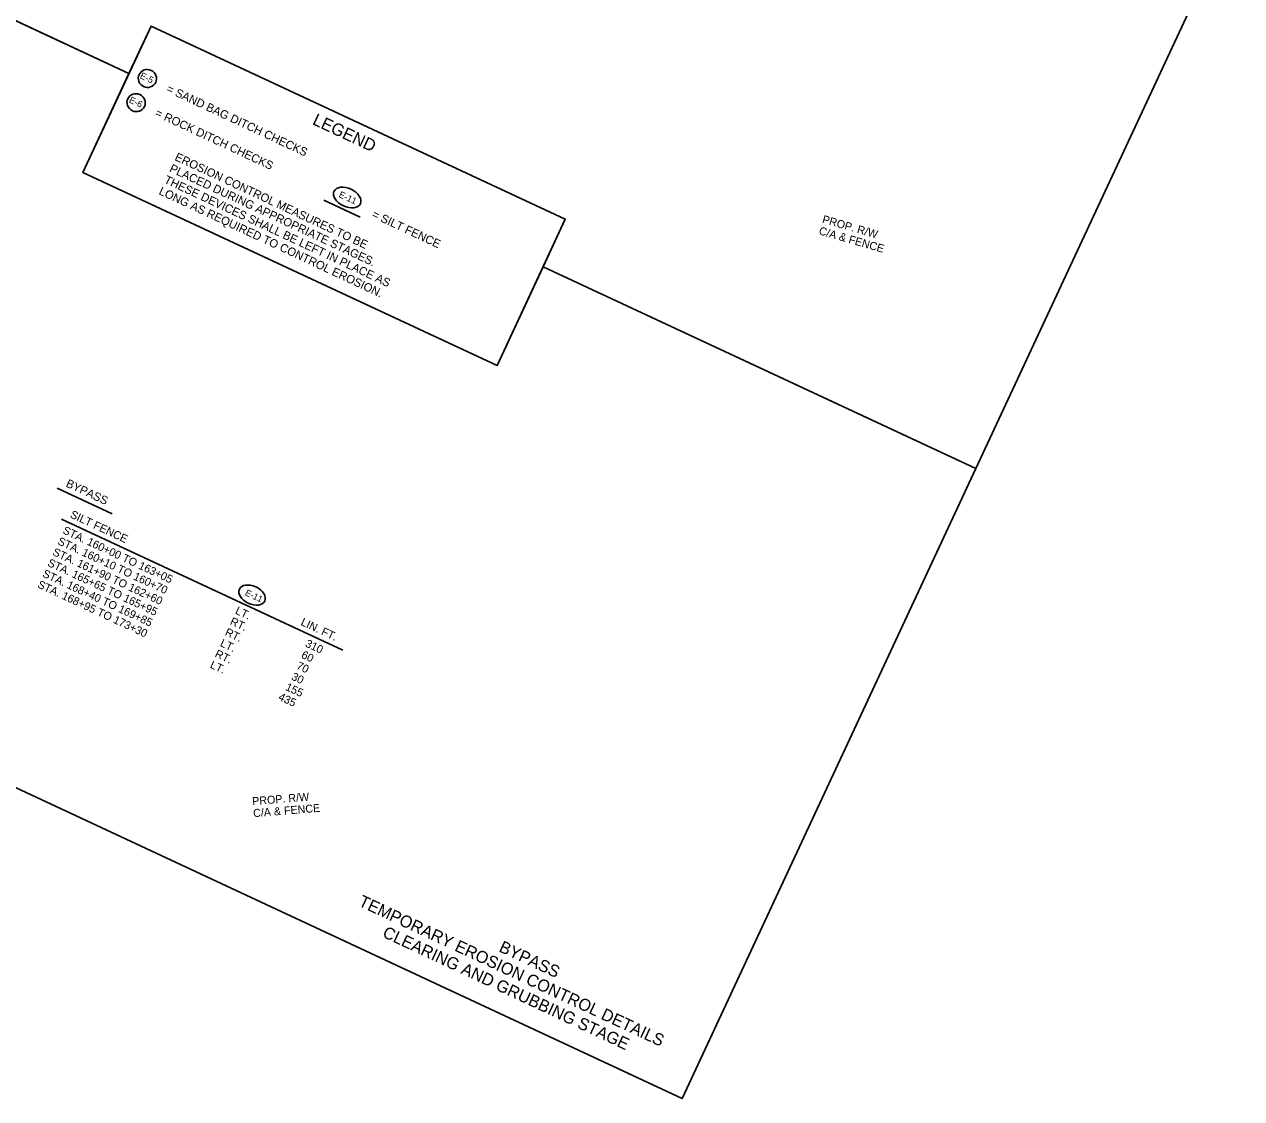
# Model space of a CAD drawing. Extents: x 980231 to 982096, y 1837566 to 1839185.
# Drawn here: x 981183 to 982096, y 1837566 to 1838371 of the extents above; entities that cross this region are included whole.
import ezdxf

# ---------------------------------------------------------------- set-up
doc = ezdxf.new("R2010")
doc.units = 0
for name, color, linetype in [('1', 7, 'Continuous'), ('44', 7, 'Continuous'), ('60', 7, 'Continuous'), ('G-Border-Sheet', 7, 'Continuous'), ('Level 1', 7, 'Continuous'), ('Level 44', 7, 'Continuous'), ('R_Draft', 7, 'Continuous')]:
    doc.layers.add(name, color=color, linetype=linetype)

msp = doc.modelspace()

# ---------------------------------------------------------------- linework, layer by layer
at = {"layer": '1'}
msp.add_ellipse((981354.22, 1837943.5), major_axis=(9.53, -4.45), ratio=0.638788, dxfattribs=at)
at = {"layer": '44'}
for p, q in [((981208.09, 1838023.65), (981249.39, 1838004.39)), ((981211.3, 1838000.53), (981422.29, 1837902.15))]:
    msp.add_line(p, q, dxfattribs=at)
at = {"layer": 'G-Border-Sheet'}
for p, q in [((981017.57, 1838448.39), (981261.89, 1838334.46)), ((981227.36, 1838260.41), (981278.52, 1838370.12)), ((981278.52, 1838370.12), (981589.08, 1838225.31)), ((981227.36, 1838260.41), (981537.92, 1838115.59)), ((981537.92, 1838115.59), (981589.08, 1838225.31)), ((981715.76, 1838122.82), (981897.02, 1838038.3))]:
    msp.add_line(p, q, dxfattribs=at)
for points in [[(980671.38, 1839184.86), (981846.87, 1838636.72), (981825.93, 1838591.82), (982096.33, 1838465.73), (981897.02, 1838038.3), (981572.45, 1838189.65), (981589.08, 1838225.31), (981278.52, 1838370.12), (981261.89, 1838334.46), (981017.57, 1838448.39), (981048.11, 1838513.87), (980662.93, 1838693.49), (980632.39, 1838628), (980451.13, 1838712.53)], [(980671.38, 1839184.86), (981846.87, 1838636.72), (981825.93, 1838591.82), (982096.33, 1838465.73), (981897.02, 1838038.3), (981572.45, 1838189.65), (981589.08, 1838225.31), (981278.52, 1838370.12), (981261.89, 1838334.46), (981017.57, 1838448.39), (981048.11, 1838513.87), (980662.93, 1838693.49), (980632.39, 1838628), (980451.13, 1838712.53)], [(980671.38, 1839184.86), (981846.87, 1838636.72), (981825.93, 1838591.82), (982096.33, 1838465.73), (981897.02, 1838038.3), (981572.45, 1838189.65), (981589.08, 1838225.31), (981278.52, 1838370.12), (981261.89, 1838334.46), (981017.57, 1838448.39), (981048.11, 1838513.87), (980662.93, 1838693.49), (980632.39, 1838628), (980451.13, 1838712.53)], [(981897.02, 1838038.3), (981676.77, 1837565.97), (981495.51, 1837650.49), (980230.88, 1838240.2), (980451.13, 1838712.53), (980632.39, 1838628), (980601.86, 1838562.52), (980987.04, 1838382.91), (981017.57, 1838448.39), (981261.89, 1838334.46), (981227.36, 1838260.41), (981537.92, 1838115.59), (981572.45, 1838189.65)], [(981897.02, 1838038.3), (981676.77, 1837565.97), (981495.51, 1837650.49), (980230.88, 1838240.2), (980451.13, 1838712.53), (980632.39, 1838628), (980601.86, 1838562.52), (980987.04, 1838382.91), (981017.57, 1838448.39), (981261.89, 1838334.46), (981227.36, 1838260.41), (981537.92, 1838115.59), (981572.45, 1838189.65)], [(981897.02, 1838038.3), (981676.77, 1837565.97), (981495.51, 1837650.49), (980230.88, 1838240.2), (980451.13, 1838712.53), (980632.39, 1838628), (980601.86, 1838562.52), (980987.04, 1838382.91), (981017.57, 1838448.39), (981261.89, 1838334.46), (981227.36, 1838260.41), (981537.92, 1838115.59), (981572.45, 1838189.65)], [(981897.02, 1838038.3), (981676.77, 1837565.97), (981495.51, 1837650.49), (980230.88, 1838240.2), (980451.13, 1838712.53), (980632.39, 1838628), (980601.86, 1838562.52), (980987.04, 1838382.91), (981017.57, 1838448.39), (981261.89, 1838334.46), (981227.36, 1838260.41), (981537.92, 1838115.59), (981572.45, 1838189.65)]]:
    msp.add_lwpolyline(points, close=True, dxfattribs=at)
at = {"layer": 'Level 1'}
for centre, major_axis, ratio in [((981275.74, 1838330.79), (-6.24, 2.91), 0.97521), ((981267.28, 1838312.66), (-6.24, 2.91), 0.97521), ((981425.59, 1838241.55), (9.93, -4.63), 0.622952)]:
    msp.add_ellipse(centre, major_axis=major_axis, ratio=ratio, dxfattribs=at)
at = {"layer": 'Level 44'}
msp.add_lwpolyline([(981408, 1838239.46), (981435.3, 1838226.74)], dxfattribs=at)

# ---------------------------------------------------------------- texts
at = {"layer": '1'}
msp.add_text('E-11', height=4.8, rotation=334.99998, dxfattribs=at).set_placement((981348.51, 1837943.56))
at = {"layer": '44'}
for s, height, rotation, p in [('BYPASS', 6.25, 335, (981214.08, 1838025.03)), ('SILT FENCE      ', 6, 334.99998, (981217.23, 1838001.91)), ('STA. 160+00 TO 163+05', 6, 334.99998, (981211.67, 1837989.98)), ('STA. 160+10 TO 160+70', 6, 334.99998, (981207.89, 1837981.87)), ('STA. 161+90 TO 162+60', 6, 334.99998, (981204.11, 1837973.76)), ('STA. 165+65 TO 165+95', 6, 334.99998, (981200.33, 1837965.65)), ('STA. 168+40 TO 169+85', 6, 334.99998, (981196.54, 1837957.54)), ('STA. 168+95 TO 173+30', 6, 334.99998, (981192.76, 1837949.43)), ('LT.', 6, 334.99998, (981341.07, 1837929.8)), ('RT.', 6, 334.99998, (981337.16, 1837921.75)), ('LIN. FT.', 6, 334.99998, (981390.21, 1837921.25)), ('RT.', 6, 334.99998, (981333.38, 1837913.64)), ('RT.', 6, 334.99998, (981325.82, 1837897.42)), ('LT.', 6, 334.99998, (981329.73, 1837905.47)), ('310', 6, 334.99998, (981393.61, 1837905.12)), ('LT.', 6, 334.99998, (981322.17, 1837889.25)), ('70', 6, 334.99998, (981386.95, 1837888.48)), ('60', 6, 334.99998, (981390.6, 1837896.65)), ('30', 6, 334.99998, (981383.17, 1837880.37)), ('155', 6, 334.99998, (981378.72, 1837872.57)), ('435', 6, 334.99998, (981373.4, 1837865.18))]:
    msp.add_text(s, height=height, rotation=rotation, dxfattribs=at).set_placement(p)
at = {"layer": '60'}
for s, p in [('TEMPORARY EROSION CONTROL DETAILS', (981433.37, 1837710.79)), ('CLEARING AND GRUBBING STAGE ', (981451.36, 1837687.51)), ('BYPASS', (981538.69, 1837676.58))]:
    msp.add_text(s, height=9, rotation=335, dxfattribs=at).set_placement(p)
at = {"layer": 'Level 1'}
for s, height, p in [('E-5 ', 4.876, (981269.69, 1838331.16)), ('= SAND BAG DITCH CHECKS', 6.25, (981289.4, 1838320.97)), ('E-6 ', 4.876, (981261.47, 1838313.02)), ('= ROCK DITCH CHECKS', 6.25, (981280.94, 1838302.84)), ('EROSION CONTROL MEASURES TO BE', 6.25, (981295.69, 1838269.78)), ('THESE DEVICES SHALL BE LEFT IN PLACE AS ', 6.25, (981287.74, 1838252.72)), ('PLACED DURING APPROPRIATE STAGES. ', 6.25, (981291.72, 1838261.25)), ('LONG AS REQUIRED TO CONTROL EROSION.', 6.25, (981283.76, 1838244.19)), ('E-11 ', 4.876, (981418.79, 1838242.08)), ('= SILT FENCE', 6.25, (981443.48, 1838226.83))]:
    msp.add_text(s, height=height, rotation=335.00001, dxfattribs=at).set_placement(p)
at = {"layer": 'Level 44'}
msp.add_text('LEGEND', height=9.143, rotation=335.00001, dxfattribs=at).set_placement((981398.89, 1838296.67))
at = {"layer": 'R_Draft'}
for s, rotation, p in [('PROP. R/W', 343.89378, (981781.32, 1838222.7)), ('C/A & FENCE', 343.89378, (981778.82, 1838214.06)), ('PROP. R/W', 4.63647, (981354.54, 1837785.94)), ('C/A & FENCE', 4.63647, (981355.27, 1837776.97))]:
    msp.add_text(s, height=6, rotation=rotation, dxfattribs=at).set_placement(p)

doc.saveas('drawing.dxf')
